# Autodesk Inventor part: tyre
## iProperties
Created: 2007-12
Part Number: tyre
Material: Rubber
Document SubType Name: Modeling
Designer: UJA2299
Density: 0.93 g/cm^3
Author: UJA2299
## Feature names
1. 押し出し_タイヤの外形_パラメータ使用 [Extrusion]
2. 面取り1 [Chamfer]
3. 押し出し2 [Extrusion]
4. シェル1
5. 押し出し3 [Extrusion]
6. 放射状パターン1 [Circular Pattern]
